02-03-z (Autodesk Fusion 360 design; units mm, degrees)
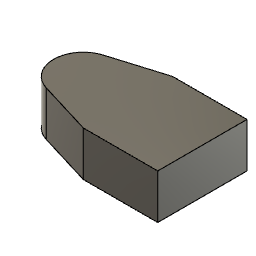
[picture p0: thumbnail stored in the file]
sketch "スケッチ" plane through (0, 0, 0) normal (0, 1, 0) x axis (1, 0, 0)
  line L1 (30, 30) -> (-5.8055, 19.1389)
  line L2 (80, 30) -> (30, 30)
  line L3 (80, -30) -> (80, 30)
  line L4 (30, -30) -> (80, -30)
  line L5 (-5.8055, -19.1389) -> (30, -30)
  arc A1 centre (0, 0) radius 20 clockwise from (-5.8055, -19.1389) to (-5.8055, 19.1389)
  point P1 (0, 0)
  point P8 (0, 0)
  point P3 (30, 30)
  point P4 (80, 30)
  point P5 (80, -30)
  horizontal L2
  perpendicular L2 L3
  perpendicular L3 L4
  tangent L1 A1
  tangent L5 A1
  equal L1 L5
  equal L2 L4
  coincident P1 P8
  dimension "d6" radius A1 = 20
  dimension "d7" distance P3 P4 = 50
  dimension "d9" distance L3 P8 = 80
  dimension "d10" distance P4 P5 = 60
extrude "押し出し" new body sketch "スケッチ" along normal blind 30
